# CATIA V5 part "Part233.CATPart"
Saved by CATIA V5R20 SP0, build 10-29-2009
Part number: DFA 168700-2 comprimido
Revision: ANY
Definition: UNKNOWN
Nomenclature: DFA 168700-2 comprimido
Source: Unknown
Bounding box of the stored display mesh (mm): x -2.8 to 2.8, y 0 to 4.04, z -2.8 to 2.8
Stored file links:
  C:\Users\Utente\Desktop\IO LAVORO\3D X SITO CF\CUMSA\3D files FA\FA 200712-21\Part233.CATPart
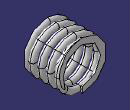
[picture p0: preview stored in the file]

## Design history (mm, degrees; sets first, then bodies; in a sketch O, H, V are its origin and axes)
Body1 "Cortar-Extruir1" (main body)
  Solid1: solid without history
